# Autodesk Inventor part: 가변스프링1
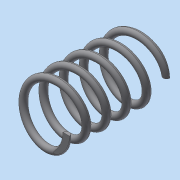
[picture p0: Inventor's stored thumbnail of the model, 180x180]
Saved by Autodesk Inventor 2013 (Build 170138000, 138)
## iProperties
Created: 2018-10
Part Number: 가변스프링1
Material: 일반
Document SubType Name: Modeling
Designer: Administrator
Density: 1 g/cm^3
Author: Administrator
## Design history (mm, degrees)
sketch "스케치1"
  geometry: L1 (0, 0)-(0, -30.473); L2 (8, 0)-(0, 0); L3 (0, -30.473)-(8, -30.473); C1 r 1 at (8, 0)
  constraints: 6 end point, 1 centre point, 1 horizontal alignment, 1 parallel, 1 perpendicular, 1 vertical
  dimensions: "d0" = 30.47293 distance of L1.start L1.end (derived); "d1" = 2 diameter of C1; "d2" = 16 diameter of L2.start L1; "d3" = 8 distance of L1.end L3.end
feature "코일1" sketch "스케치1" pitch "d4" = 10; turns "d6" = 5; dims "d5" = 30.47293 (= d0), "d7" = 0, angle "d8" = 90 deg, angle "d9" = 90 deg, "d10" = 0, "d11" = 0
sketch "스케치2"
  geometry: L1 (-30.473, 10)-(0, 10); L2 (0, 10)-(0, -10); L3 (0, -10)-(-30.473, -10); L4 (-30.473, -10)-(-30.473, 10); 2 further points
  constraints: 8 end point, 2 parallel, 1 coincident, 1 horizontal, 1 midpoint, 1 perpendicular
  dimensions: "d12" = 30.47293 distance of L2.end L3.end (derived); "d14" = 20 distance of L1.end L2.end
extrude "돌출1" sketch "스케치2" stored distance "d15" = 0; taper "d16" = 0 deg
node "솔리드1"
